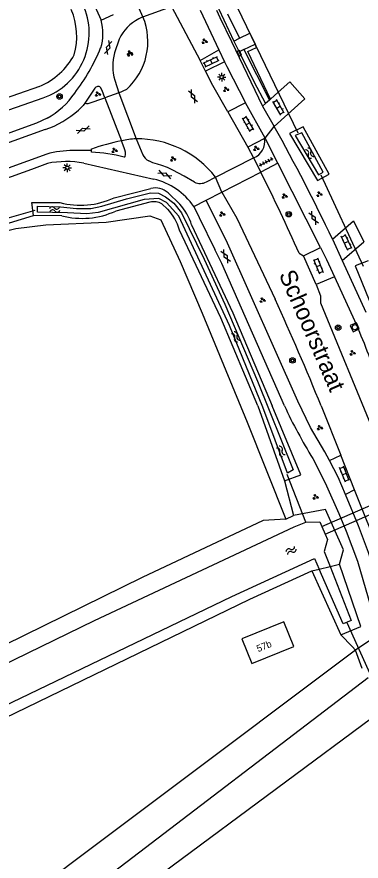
# Model space of a CAD drawing. Extents: x 134297 to 137000, y 403500 to 406000.
# Drawn here: x 136193 to 136243.4, y 404433.4 to 404556.9 of the extents above; entities that cross this region are included whole.
import ezdxf

# ---------------------------------------------------------------- set-up
doc = ezdxf.new("R2010")
doc.units = 0
for name, color, linetype in [('gg-afsc-draadraster', 7, 'Continuous'), ('gg-afsc-erfafscheiding', 7, 'Continuous'), ('gg-afsc-lijn draadraster', 7, 'Continuous'), ('gg-anno-huisnummerreeks BGT', 7, 'Continuous'), ('gg-anno-openbare ruimte label', 7, 'Continuous'), ('gg-bbg-hoofdgebouw', 7, 'Continuous'), ('gg-knt-bronhoudergrens', 7, 'Continuous'), ('gg-knt-verharding', 7, 'Continuous'), ('gg-knt-verharding nz', 7, 'Continuous'), ('gg-kntw-bovenkant insteek waterloop', 7, 'Continuous'), ('gg-kntw-waterlijn', 7, 'Continuous'), ('gg-kwrk-duiker nz buis', 7, 'Continuous'), ('gt-grn-groengrens', 7, 'Continuous'), ('gt-grn-vlakafsluiter', 7, 'Continuous'), ('gt-grn-weggrens', 7, 'Continuous'), ('gt-symb-boom', 7, 'Continuous'), ('gt-symb-gesloten verharding', 7, 'Continuous'), ('gt-symb-groenvak', 7, 'Continuous'), ('gt-symb-klinker verharding', 7, 'Continuous'), ('gt-symb-kolk', 7, 'Continuous'), ('gt-symb-lichtmast', 7, 'Continuous'), ('gt-symb-rioolschacht', 7, 'Continuous'), ('gt-symb-tegel verharding', 7, 'Continuous'), ('gt-symb-watersymbool', 7, 'Continuous')]:
    doc.layers.add(name, color=color, linetype=linetype)

# ---------------------------------------------------------------- blocks, each defined once
blk = doc.blocks.new('gt0-BOOM')
at = {"layer": 'gt-symb-boom'}
for radius in [0.4, 0.2]:
    blk.add_circle((0, 0), radius, dxfattribs=at)
blk = doc.blocks.new('gt0-WA')
at = {"layer": 'gt-symb-watersymbool'}
for centre, start, end in [((-0.32, 0.02), 28.0725, 151.9275), ((0.43, 0.42), 208.0725, 331.9275), ((-0.32, -0.43), 28.0725, 151.9275), ((0.43, -0.03), 208.0725, 331.9275)]:
    blk.add_arc(centre, 0.425, start, end, dxfattribs=at)
blk = doc.blocks.new('gt0-GRVAK')
at = {"layer": 'gt-symb-groenvak'}
for p, q in [((-0.11, 0.19), (-0.23, 0.24)), ((-0.18, 0.15), (0.09, 0.15)), ((-0.09, 0.21), (-0.16, 0.32)), ((-0.05, 0.21), (-0.05, 0.39)), ((0, 0.21), (0.06, 0.32)), ((0.01, 0.19), (0.13, 0.24)), ((0.26, -0.05), (0.2, 0.06)), ((0.3, -0.05), (0.3, 0.13)), ((0.35, -0.05), (0.41, 0.06)), ((-0.24, -0.23), (-0.36, -0.18)), ((-0.32, -0.26), (-0.05, -0.26)), ((-0.23, -0.21), (-0.29, -0.09)), ((-0.18, -0.2), (-0.18, -0.02)), ((-0.14, -0.21), (-0.07, -0.09)), ((-0.12, -0.23), (0, -0.18)), ((0.24, -0.07), (0.12, -0.02)), ((0.17, -0.11), (0.44, -0.11)), ((0.37, -0.07), (0.49, -0.02))]:
    blk.add_line(p, q, dxfattribs=at)
blk = doc.blocks.new('gt0-TEG1')
at = {"layer": 'gt-symb-tegel verharding'}
for p, q in [((-1.12, 0), (1.12, 0)), ((-0.9, -0.25), (-0.9, 0.25)), ((-0.45, -0.25), (-0.45, 0.25)), ((0, -0.25), (0, 0.25)), ((0.45, -0.25), (0.45, 0.25)), ((0.9, -0.25), (0.9, 0.25))]:
    blk.add_line(p, q, dxfattribs=at)
blk = doc.blocks.new('gt0-KL1')
at = {"layer": 'gt-symb-klinker verharding'}
for p, q in [((-1.15, 0.3), (1.15, 0.3)), ((-1, -0.3), (-1, 0.3)), ((-0.5, 0.3), (-0.5, 0.45)), ((0, -0.3), (0, 0.3)), ((0.5, 0.3), (0.5, 0.45)), ((1, -0.3), (1, 0.3)), ((-1.15, -0.3), (1.15, -0.3)), ((-0.5, -0.45), (-0.5, -0.3)), ((0.5, -0.45), (0.5, -0.3))]:
    blk.add_line(p, q, dxfattribs=at)
blk = doc.blocks.new('gt0-KOLK')
at = {"layer": 'gt-symb-kolk'}
blk.add_lwpolyline([(0, 0), (0.38, 0), (0.38, 0.4), (-0.38, 0.4), (-0.38, 0), (0, 0)], dxfattribs=at)
blk = doc.blocks.new('gt0-GESVH1')
at = {"layer": 'gt-symb-gesloten verharding'}
for p, q in [((-0.99, -0.26), (0.01, 0.24)), ((0.01, -0.26), (-0.99, 0.24)), ((0.01, 0.24), (1.01, -0.26)), ((1.01, 0.24), (0.01, -0.26))]:
    blk.add_line(p, q, dxfattribs=at)
blk = doc.blocks.new('gt0-LMAST')
at = {"layer": 'gt-symb-lichtmast'}
for p, q in [((-0.18, 0.17), (-0.45, 0.44)), ((-0.01, 0.25), (-0.01, 0.62)), ((0.17, 0.17), (0.44, 0.44)), ((-0.26, 0), (-0.63, 0)), ((-0.18, -0.18), (-0.45, -0.45)), ((-0.01, -0.25), (-0.01, -0.63)), ((0.44, -0.45), (0.17, -0.18)), ((0.24, 0), (0.62, 0))]:
    blk.add_line(p, q, dxfattribs=at)
blk.add_circle((-0.01, 0), 0.25, dxfattribs=at)
blk = doc.blocks.new('gt0-RS')
at = {"layer": 'gt-symb-rioolschacht'}
blk.add_lwpolyline([(-0.5, -0.5), (0.5, -0.5), (0.5, 0.5), (-0.5, 0.5)], close=True, dxfattribs=at)
blk.add_circle((0, 0), 0.375, dxfattribs=at)

msp = doc.modelspace()

# ---------------------------------------------------------------- linework, layer by layer
at = {"layer": 'gg-afsc-draadraster'}
msp.add_lwpolyline([(136027, 404470.76), (136054.87, 404479.77), (136100.69, 404494.3), (136117.79, 404500.1), (136188.91, 404524.97), (136192.84, 404525.94), (136197.24, 404526.47), (136206.06, 404526.86), (136212.49, 404527.78), (136214.08, 404527.22), (136216.9, 404521.12), (136220.14, 404513.53), (136226.74, 404497.62), (136232.4, 404483.42)], dxfattribs=at)
at = {"layer": 'gg-afsc-erfafscheiding'}
msp.add_line((136223.87, 404557.34), (136225.63, 404553.76), dxfattribs=at)
at = {"layer": 'gg-afsc-lijn draadraster'}
msp.add_lwpolyline([(136027, 404470.76), (136054.87, 404479.77), (136100.69, 404494.3), (136117.79, 404500.1), (136188.91, 404524.97), (136192.84, 404525.94), (136197.24, 404526.47), (136206.06, 404526.86), (136212.49, 404527.78), (136214.08, 404527.22), (136216.9, 404521.12), (136220.14, 404513.53), (136226.74, 404497.62), (136232.4, 404483.42)], dxfattribs=at)
at = {"layer": 'gg-bbg-hoofdgebouw'}
msp.add_lwpolyline([(136233.58, 404464.8), (136232.12, 404468.41), (136225.94, 404465.9), (136227.41, 404462.29), (136233.58, 404464.8)], dxfattribs=at)
at = {"layer": 'gg-knt-bronhoudergrens'}
for points in [[(136242.62, 404464.28), (136129.69, 404379.67), (136126.5, 404377.04)], [(136246.33, 404455.28), (136215.76, 404432.64), (136169.13, 404397.65), (136148.62, 404382.43)]]:
    msp.add_lwpolyline(points, dxfattribs=at)
at = {"layer": 'gg-knt-verharding'}
for p, q in [((136203.6, 404560.23), (136205.33, 404556.42)), ((136215.63, 404558.42), (136219.83, 404550.53)), ((136219.84, 404557.9), (136222.6, 404552.06)), ((136222.23, 404557.89), (136222.75, 404556.8)), ((136211.47, 404556.89), (136210.86, 404556.59)), ((136222.75, 404556.8), (136224.46, 404553.27)), ((136207.99, 404553.65), (136207.32, 404551.64)), ((136224.8, 404553.36), (136225.63, 404553.76)), ((136224.46, 404553.27), (136229, 404543.85)), ((136224.8, 404553.36), (136225.57, 404551.8)), ((136226.24, 404552.1), (136227.89, 404552.89)), ((136219.83, 404550.53), (136222.6, 404552.06)), ((136222.6, 404552.06), (136223.42, 404550.33)), ((136220.62, 404548.97), (136219.83, 404550.53)), ((136223.42, 404550.33), (136220.62, 404548.97)), ((136207.33, 404547.64), (136207.95, 404545.79)), ((136204.43, 404546.45), (136202.94, 404544.26)), ((136207.95, 404545.79), (136209.09, 404546.31)), ((136232.99, 404547.38), (136231.29, 404545.87)), ((136231.29, 404545.87), (136230.14, 404544.86)), ((136226.47, 404544.3), (136223.89, 404542.99)), ((136229.37, 404539.17), (136226.47, 404544.3)), ((136229.41, 404544.21), (136229, 404543.85)), ((136229, 404543.85), (136230.71, 404540.85)), ((136229.98, 404544.72), (136229.41, 404544.21)), ((136230.14, 404544.86), (136229.98, 404544.72)), ((136235.18, 404544.91), (136230.71, 404540.85)), ((136223.89, 404542.99), (136226.84, 404537.86)), ((136210.47, 404539.06), (136211.45, 404536.71)), ((136229.28, 404539.12), (136226.84, 404537.86)), ((136229.37, 404539.17), (136229.28, 404539.12)), ((136231.22, 404535.5), (136229.37, 404539.17)), ((136208.73, 404537.73), (136208.34, 404538.77)), ((136226.84, 404537.86), (136227.67, 404536.26)), ((136203.92, 404537.36), (136203.92, 404537.57)), ((136203.92, 404537.12), (136203.92, 404537.36)), ((136202.81, 404535.48), (136213.07, 404533.17)), ((136227.67, 404536.26), (136228.73, 404534.18)), ((136231.22, 404535.5), (136228.73, 404534.18)), ((136237.49, 404523.15), (136231.22, 404535.5)), ((136220.76, 404532.76), (136222.08, 404533.46)), ((136220.71, 404530.1), (136223.02, 404531.25)), ((136223.85, 404523.78), (136220.71, 404530.1)), ((136239.22, 404524.36), (136240.66, 404521.24)), ((136234.98, 404521.96), (136237.49, 404523.15)), ((136240.66, 404521.24), (136243.81, 404523.97)), ((136234.34, 404522.31), (136234.98, 404521.96)), ((136236.82, 404517.74), (136234.98, 404521.96)), ((136240.66, 404521.24), (136244.13, 404513.69)), ((136239.51, 404518.87), (136236.82, 404517.74)), ((136239.51, 404518.87), (136242.97, 404511.29)), ((136237.57, 404500), (136240.46, 404492.77)), ((136236.35, 404492.29), (136236.92, 404491.15)), ((136238.79, 404491.98), (136240.46, 404492.77)), ((136242.46, 404487.73), (136240.46, 404492.77)), ((136242.46, 404487.73), (136241.13, 404487.04)), ((136243.03, 404482.44), (136241.13, 404487.04)), ((136249.56, 404469.81), (136242.46, 404487.73)), ((136246.03, 404466.53), (136242.62, 404464.28)), ((136243.55, 404461.56), (136242.62, 404464.28))]:
    msp.add_line(p, q, dxfattribs=at)
for points in [[(136216.01, 404571.98), (136222.58, 404558.03), (136224.8, 404553.36)], [(136225.63, 404553.76), (136227.13, 404554.49), (136227.89, 404552.89)], [(136226.24, 404552.1), (136225.67, 404551.83), (136225.57, 404551.8)], [(136225.57, 404551.8), (136227.73, 404547.42), (136229.41, 404544.21)], [(136223.42, 404550.33), (136223.75, 404549.64), (136226.47, 404544.3)], [(136223.89, 404542.99), (136221.7, 404546.84), (136220.62, 404548.97)], [(136205.91, 404545.05), (136205.5, 404546.13), (136205.25, 404546.57)], [(136202.94, 404544.26), (136203.18, 404544.2), (136203.43, 404544.21), (136205.91, 404545.05)], [(136197.46, 404542.1), (136195.9, 404541.36), (136160.84, 404528.67), (136124.12, 404515.41), (136117.65, 404513.15)], [(136208.74, 404536.4), (136208.84, 404536.4), (136208.88, 404536.47)], [(136197.49, 404535.45), (136195.13, 404534.58), (136162.9, 404522.97), (136127.36, 404510.1), (136113.62, 404505.3), (136099.76, 404500.63), (136086.34, 404496.28), (136076.86, 404493.32), (136066.07, 404490.19), (136055.56, 404487.24), (136045.09, 404484), (136034.7, 404480.64), (136023.56, 404476.68), (136011.23, 404471.9), (136004.74, 404469.15), (135995.87, 404465.09), (135985.92, 404460.27), (135976.35, 404455.35), (135965.54, 404449.33), (135957.74, 404444.76)], [(136219.01, 404532.71), (136217.53, 404533.59), (136215.85, 404534.48), (136215.06, 404534.86), (136214.25, 404535.17), (136213.58, 404535.35), (136212.91, 404535.56), (136212.32, 404535.84)], [(136223.02, 404531.25), (136225.23, 404527.43), (136230.82, 404515.6)], [(136218.91, 404529.16), (136219.72, 404527.56), (136222.02, 404522.89)], [(136239.22, 404524.36), (136242.28, 404527.07), (136243.81, 404523.97)], [(136232.19, 404500), (136223, 404520.82), (136222.02, 404522.89)], [(136238.79, 404491.98), (136238.09, 404493.29), (136236.03, 404496.85), (136234.13, 404500.67), (136223.85, 404523.78)], [(136237.49, 404523.15), (136238.36, 404521.4), (136239.51, 404518.87)], [(136236.82, 404517.74), (136237.47, 404516.09), (136237.45, 404515.08), (136245.24, 404496.22)], [(136241.13, 404487.04), (136240.07, 404489.57), (136238.79, 404491.98)], [(136236.92, 404491.15), (136238.33, 404488.31), (136240.16, 404484.25), (136241.24, 404481.65), (136242.9, 404477.26), (136246.03, 404466.53)]]:
    msp.add_lwpolyline(points, dxfattribs=at)
for centre, radius, start, end in [((136198.74, 404554.47), 6.88, 342.1088, 16.4811), ((136213.76, 404550.87), 6.41, 116.9215, 154.3394), ((136202.79, 404553.29), 9.4, 312.0759, 22.5376), ((136177.58, 404563.85), 29.99, 322.8167, 337.4573), ((136214.51, 404549.66), 7.45, 164.5887, 195.6695), ((136204.89, 404546.18), 0.534, 47.665, 149.7853), ((136191.82, 404552.38), 11.73, 298.7518, 325.4554), ((135996.94, 404409.88), 267.96, 25.2913, 29.2608), ((136210.62, 404524.52), 14.54, 37.9449, 90.5788), ((136226.76, 404538.66), 2.57, 290.764, 10.4122), ((136214.9, 404505.82), 33.59, 101.2564, 109.0784), ((136206.78, 404536.85), 2.14, 349.5953, 24.2082), ((136202.24, 404509.58), 27.59, 76.3785, 86.5134), ((136213.21, 404537.6), 1.97, 206.648, 243.0895), ((136200.22, 404521.93), 13.8, 79.2034, 101.4217), ((135994.88, 404416.38), 261.84, 23.8636, 26.7378), ((136210.77, 404523.56), 9.88, 34.491, 76.5369), ((136219.84, 404534.53), 2, 245.6379, 297.5116), ((135821.09, 404328.82), 450.29, 22.3436, 24.5068), ((136198.35, 404490.95), 49.03, 13.4039, 24.5051), ((136301.02, 404532.15), 75.97, 205.0405, 211.6522), ((136135.85, 404440.24), 115.19, 14.8813, 21.4921)]:
    msp.add_arc(centre, radius, start, end, dxfattribs=at)
at = {"layer": 'gg-knt-verharding nz'}
for p, q in [((136211.47, 404556.89), (136210.61, 404558.82)), ((136205.33, 404556.42), (136207.17, 404557.24)), ((136207.95, 404545.79), (136205.91, 404545.05)), ((136203.92, 404537.36), (136201.23, 404537.33)), ((136223.02, 404531.25), (136222.08, 404533.46)), ((136218.91, 404529.16), (136220.71, 404530.1))]:
    msp.add_line(p, q, dxfattribs=at)
for points in [[(136202.94, 404544.26), (136202.73, 404543.95), (136202.03, 404543.27)], [(136197.15, 404540.4), (136161.45, 404527.53), (136124.76, 404514.25), (136111.52, 404509.6), (136099.13, 404505.43), (136084.9, 404500.78), (136071.52, 404496.67), (136060.9, 404493.69), (136050.35, 404490.61), (136039.81, 404487.34), (136029.4, 404483.84), (136019.03, 404480.06), (136009.73, 404476.4), (136000.5, 404472.45), (135991.4, 404468.23), (135983.33, 404464.29), (135976.2, 404460.63), (135968.25, 404456.35), (135961.29, 404452.4), (135955.27, 404448.86)], [(136197.38, 404536.83), (136126.86, 404511.31), (136112.69, 404506.32), (136099.4, 404501.86), (136086.05, 404497.55), (136076.48, 404494.56), (136065.87, 404491.48), (136055.28, 404488.5), (136044.76, 404485.25), (136034.33, 404481.86), (136023.04, 404477.86), (136010.9, 404473.14), (136004.49, 404470.44), (135995.36, 404466.29), (135985.46, 404461.47), (135975.71, 404456.46), (135965.21, 404450.62), (135957.08, 404445.86)]]:
    msp.add_lwpolyline(points, dxfattribs=at)
for centre, radius, start, end in [((136192.69, 404553.55), 13.89, 288.7397, 312.2499), ((136210.98, 404527.3), 11.77, 92.4749, 102.9643), ((136201.02, 404524.02), 13.31, 89.0626, 105.8599)]:
    msp.add_arc(centre, radius, start, end, dxfattribs=at)
at = {"layer": 'gg-kntw-bovenkant insteek waterloop'}
for p, q in [((136196.3, 404546.72), (136115.55, 404518.56)), ((136207.24, 404530.41), (136212.61, 404531.79)), ((136215.15, 404531.14), (136216.87, 404529.51)), ((136212.49, 404529.78), (136207.49, 404528.49)), ((136215.09, 404528.76), (136214.26, 404529.55)), ((136199.57, 404527.8), (136195.43, 404527.83)), ((136228.28, 404500), (136232.18, 404489.03)), ((136232.4, 404483.42), (136233.52, 404483.98)), ((136236.18, 404475.84), (136240.43, 404466.52))]:
    msp.add_line(p, q, dxfattribs=at)
for points in [[(136115.55, 404518.56), (136116.11, 404516.88), (136196.86, 404545.05)], [(136234.92, 404540.83), (136232.91, 404539.84), (136237.04, 404532.96), (136238.75, 404533.91), (136234.92, 404540.83)], [(136195.43, 404527.83), (136195.19, 404529.74), (136199.32, 404529.72)], [(136228.28, 404500), (136222.87, 404512.88), (136216.82, 404525.71)], [(136218.6, 404526.46), (136224.65, 404513.62), (136230.37, 404500)], [(136244.43, 404521.21), (136242.57, 404520.5), (136250.57, 404500.86), (136252.66, 404501.63)], [(136232.18, 404489.03), (136234.61, 404489.92), (136230.37, 404500)], [(136240.26, 404476.86), (136240.86, 404478.92), (136238.19, 404484.83), (136233.52, 404483.98)], [(136232.4, 404483.42), (136229.09, 404483.22), (136211.35, 404474.91), (136179.65, 404459.33), (136143.55, 404441.91), (136089.18, 404415.38), (136050.09, 404396.55), (136020.57, 404382.16), (135988.75, 404366.64), (135931.54, 404338.35), (135877.73, 404313.16)], [(136108.02, 404414.04), (136227.12, 404471.72), (136236.18, 404475.84)], [(136240.43, 404466.52), (136243.37, 404467.72), (136240.26, 404476.86)]]:
    msp.add_lwpolyline(points, dxfattribs=at)
for centre, radius, start, end in [((136193.55, 404554.53), 10.05, 289.2197, 24.9426), ((136191.72, 404554.05), 10.05, 344.4419, 22.8555), ((136192.49, 404556.05), 10.07, 292.2018, 332.2114), ((136213.28, 404529.17), 2.71, 46.5394, 104.4245), ((136202.31, 404541.19), 11.85, 255.3814, 294.5755), ((136213.04, 404527.18), 2.66, 62.8343, 102.0146), ((136211.14, 404524.24), 7.78, 16.5649, 42.6085), ((136202.56, 404539.27), 11.85, 255.3814, 294.5755), ((136209.37, 404523.5), 7.78, 16.5649, 42.6085)]:
    msp.add_arc(centre, radius, start, end, dxfattribs=at)
at = {"layer": 'gg-kntw-waterlijn'}
msp.add_line((136237.66, 404482.34), (136238.14, 404481.24), dxfattribs=at)
for points in [[(136233.78, 404539.55), (136237.16, 404533.77), (136237.87, 404534.18), (136234.73, 404539.95), (136233.78, 404539.55)], [(136232.66, 404490.17), (136229.02, 404499.8), (136224.16, 404511.74), (136216.71, 404527.75), (136214.94, 404529.75), (136213.81, 404530.35), (136211.65, 404530.2), (136204.93, 404528.26), (136203.25, 404528.06), (136200.44, 404528.24), (136196.02, 404528.33), (136196.03, 404529.19), (136199.42, 404529.12), (136201.76, 404528.87), (136203.83, 404528.85), (136205.45, 404529.2), (136209.08, 404530.3), (136212.59, 404531.16), (136213.74, 404531.09), (136214.79, 404530.58), (136215.99, 404529.66), (136217.13, 404528.24), (136220.43, 404521.45), (136223.44, 404514.89), (136228.25, 404503.63), (136233.47, 404490.63), (136232.66, 404490.17)], [(135884.16, 404313.75), (135898.53, 404320.11), (135926.42, 404333.8), (135951.05, 404345.14), (135965.34, 404352.44), (136021.67, 404379.51), (136084.87, 404410.41), (136126.48, 404430.96), (136169.18, 404451.47), (136204.36, 404468.59), (136233.6, 404482.32), (136235.31, 404482.99), (136237.37, 404483.02), (136237.66, 404482.34)], [(136238.14, 404481.24), (136238.48, 404480.44), (136238.03, 404478.71), (136238.88, 404476.52)], [(135885.33, 404308.76), (135911.22, 404321.24), (135977.2, 404352.57), (135993.05, 404360.74), (136022.28, 404374.43), (136052.47, 404388.81), (136081.4, 404402.63), (136112.63, 404418.58), (136144.64, 404434.05), (136190.99, 404456.03), (136224.47, 404472.11), (136236.59, 404477.67), (136237.28, 404476.11)], [(136238.88, 404476.52), (136241.97, 404468.6), (136240.8, 404468.1), (136237.28, 404476.11)]]:
    msp.add_lwpolyline(points, dxfattribs=at)
at = {"layer": 'gg-kwrk-duiker nz buis'}
for p, q in [((136200.65, 404609.29), (136234.15, 404539.95)), ((136237.53, 404533.8), (136243.74, 404520.45)), ((136195.64, 404528.57), (136185.91, 404525.77)), ((136237.66, 404482.34), (136257.03, 404490.79)), ((136235.31, 404482.99), (136232.6, 404489.96)), ((136238.14, 404481.24), (136257.49, 404489.69)), ((136241.31, 404468.31), (136245.33, 404459.43))]:
    msp.add_line(p, q, dxfattribs=at)
at = {"layer": 'gt-grn-groengrens'}
for p, q in [((136226.24, 404552.1), (136229.98, 404544.72)), ((136186.6, 404525.12), (136195.43, 404527.83)), ((136232.18, 404489.03), (136233.52, 404483.98))]:
    msp.add_line(p, q, dxfattribs=at)
for points in [[(136230.14, 404544.86), (136226.83, 404551.81), (136228.12, 404552.43), (136227.89, 404552.89)], [(136240.43, 404466.52), (136242.11, 404464.8), (136242.62, 404464.28)]]:
    msp.add_lwpolyline(points, dxfattribs=at)
at = {"layer": 'gt-grn-vlakafsluiter'}
for p, q in [((136232.99, 404547.38), (136235.18, 404544.91)), ((136236.18, 404475.84), (136237.28, 404476.11)), ((136237.28, 404476.11), (136238.88, 404476.52)), ((136238.88, 404476.52), (136240.26, 404476.86)), ((136128.9, 404372.27), (136244.44, 404460.24))]:
    msp.add_line(p, q, dxfattribs=at)
at = {"layer": 'gt-grn-weggrens'}
for p, q in [((136211.47, 404556.89), (136215.63, 404558.42)), ((136205.91, 404545.05), (136208.34, 404538.77)), ((136207.95, 404545.79), (136210.47, 404539.06)), ((136229.37, 404539.17), (136230.71, 404540.85)), ((136222.08, 404533.46), (136227.67, 404536.26)), ((136223.02, 404531.25), (136228.73, 404534.18))]:
    msp.add_line(p, q, dxfattribs=at)

# ---------------------------------------------------------------- block references
at = {"layer": 'gt-symb-boom'}
for p in [(136199.26, 404545.25), (136232.83, 404528.03), (136240.06, 404511.43), (136233.37, 404506.64)]:
    msp.add_blockref('gt0-BOOM', p, dxfattribs=at)
at = {"layer": 'gt-symb-gesloten verharding'}
for p, rotation in [((136206.36, 404552.4), 73.01526746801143), ((136218.79, 404545.26), 115.97571465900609), ((136202.71, 404540.41), 19.939047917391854), ((136214.67, 404533.85), -24.078837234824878), ((136236.46, 404527.48), 118.99897714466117), ((136223.59, 404521.84), 118.99897714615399)]:
    msp.add_blockref('gt0-GESVH1', p, dxfattribs=dict(at, rotation=rotation))
at = {"layer": 'gt-symb-groenvak'}
for p in [(136220.48, 404553.32), (136209.52, 404551.61), (136209.57, 404551.46), (136223.63, 404546.28), (136204.84, 404545.6), (136207.28, 404537.35), (136228.04, 404537.65), (136215.86, 404536.1), (136232.2, 404530.67), (136237.29, 404530.95), (136223.05, 404528.05), (136228.97, 404515.45), (136242.14, 404507.74), (136237.35, 404496.8), (136236.72, 404486.67)]:
    msp.add_blockref('gt0-GRVAK', p, dxfattribs=at)
at = {"layer": 'gt-symb-klinker verharding'}
for p, rotation in [((136221.47, 404550.34), 25.97571465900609), ((136231.34, 404543.66), 120.00072777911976), ((136226.86, 404541.24), 120.00072778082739), ((136241.28, 404523.91), 115.02727879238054), ((136237.17, 404520.47), -67.92205836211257), ((136240.97, 404490.01), 112.02484593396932)]:
    msp.add_blockref('gt0-KL1', p, dxfattribs=dict(at, rotation=rotation))
at = {"layer": 'gt-symb-kolk', "rotation": -64.79277878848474}
msp.add_blockref('gt0-KOLK', (136225.39, 404551.48), dxfattribs=at)
at = {"layer": 'gt-symb-lichtmast'}
for p in [(136223.01, 404548.09), (136200.39, 404534.82)]:
    msp.add_blockref('gt0-LMAST', p, dxfattribs=at)
at = {"layer": 'gt-symb-rioolschacht', "rotation": -65.48492926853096}
msp.add_blockref('gt0-RS', (136242.49, 404511.5), dxfattribs=at)
at = {"layer": 'gt-symb-tegel verharding', "rotation": 27.846622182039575}
msp.add_blockref('gt0-TEG1', (136229.53, 404535.67), dxfattribs=at)
at = {"layer": 'gt-symb-watersymbool'}
for p, rotation in [((136235.91, 404536.9), 126.01052540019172), ((136198.6, 404528.71), -171.02737338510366), ((136225.1, 404510.03), 126.01052540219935), ((136231.7, 404493.3), 126.01052540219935), ((136233.22, 404478.86), -147.9946167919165)]:
    msp.add_blockref('gt0-WA', p, dxfattribs=dict(at, rotation=rotation))

# ---------------------------------------------------------------- texts
at = {"layer": 'gg-anno-huisnummerreeks BGT'}
msp.add_text('57b', height=1, rotation=22, dxfattribs=at).set_placement((136228.35, 404463.96))
at = {"layer": 'gg-anno-openbare ruimte label'}
msp.add_text('Schoorstraat', height=2.5, rotation=293.6, dxfattribs=at).set_placement((136231.33, 404519.22))

doc.saveas('drawing.dxf')
